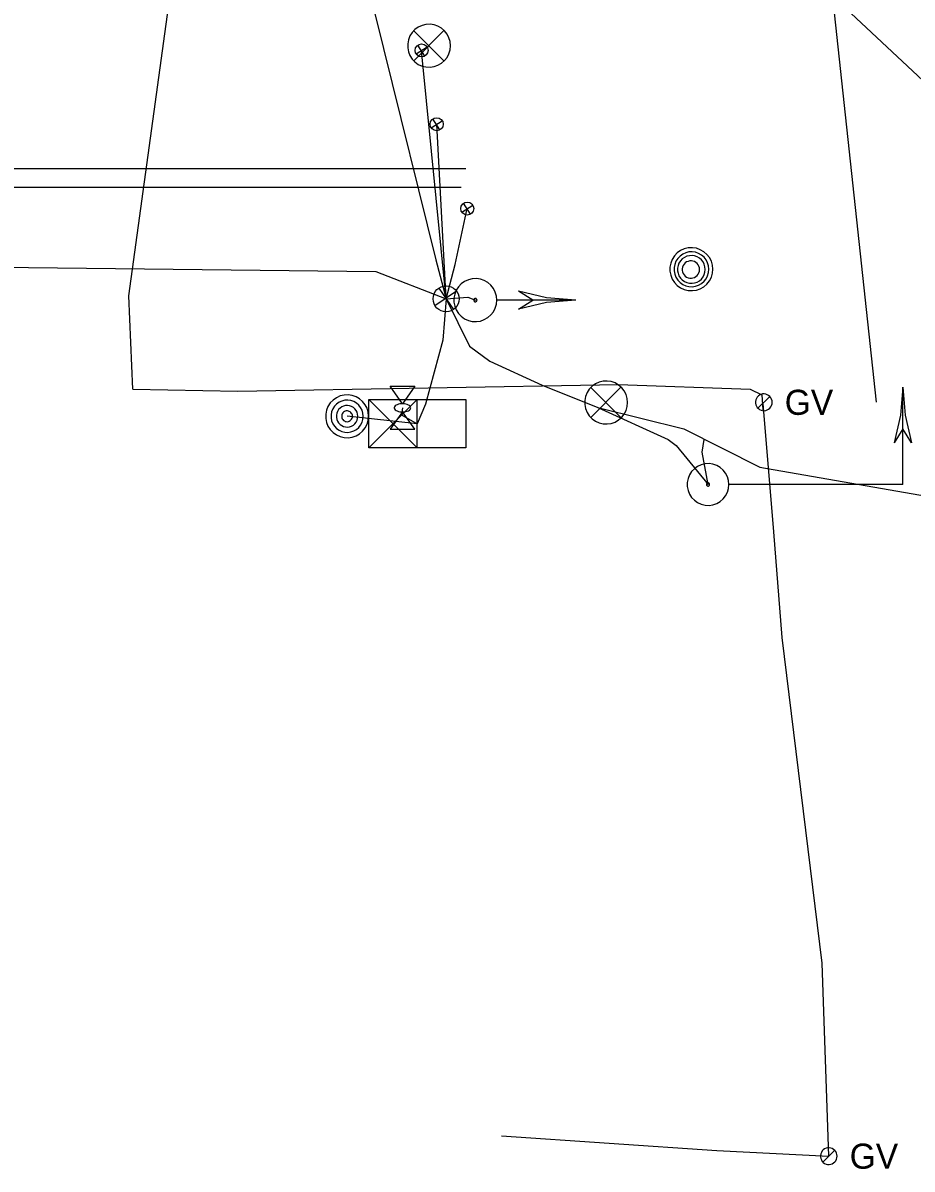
# Model space of a CAD drawing. Extents: x 600849 to 606371, y 330010 to 403088.
# Drawn here: x 604922.6 to 605059.1, y 349725.2 to 349901.2 of the extents above; entities that cross this region are included whole.
import ezdxf

# ---------------------------------------------------------------- set-up
doc = ezdxf.new("R2010")
doc.units = 0
for name, color, linetype in [('E_MISCPROP', 7, 'Continuous'), ('E_SIG', 7, 'Continuous'), ('E_SIG_Conduit', 7, 'Continuous'), ('E_UTL_AG', 7, 'Continuous'), ('E_UTL_E_UG', 7, 'Continuous'), ('E_UTL_G', 7, 'Continuous'), ('E_UTL_G_UG', 7, 'Continuous'), ('E_UTL_Loop_UG', 7, 'Continuous'), ('E_UTL_MH', 7, 'Continuous'), ('E_UTL_Overhead', 7, 'Continuous'), ('E_UTL_T_UG', 7, 'Continuous')]:
    doc.layers.add(name, color=color, linetype=linetype)

# ---------------------------------------------------------------- blocks, each defined once
blk = doc.blocks.new('_U336')
at = {"layer": 'E_SIG'}
for p, q in [((-6.1, 0.4), (6.1, 0.4)), ((0, 6.1), (0, -6.1))]:
    blk.add_line(p, q, dxfattribs=at)
blk.add_circle((0, 0), 6.1, dxfattribs=at)
blk = doc.blocks.new('_U337')
at = {"layer": 'E_SIG'}
for p, q in [((-6.1, 0.4), (6.1, 0.4)), ((0, 6.1), (0, -6.1))]:
    blk.add_line(p, q, dxfattribs=at)
blk.add_circle((0, 0), 6.1, dxfattribs=at)
blk = doc.blocks.new('_U338')
at = {"layer": 'E_SIG'}
for p, q in [((-6.1, 0.4), (6.1, 0.4)), ((0, 6.1), (0, -6.1))]:
    blk.add_line(p, q, dxfattribs=at)
blk.add_circle((0, 0), 6.1, dxfattribs=at)
blk = doc.blocks.new('_U347')
at = {"layer": 'E_SIG'}
for p, q in [((0, 6.1), (0, -6.1)), ((-6.09, 0.4), (6.1, 0.4))]:
    blk.add_line(p, q, dxfattribs=at)
blk.add_circle((0, 0.01), 6.1, dxfattribs=at)

msp = doc.modelspace()

# ---------------------------------------------------------------- linework, layer by layer
at = {"layer": 'E_MISCPROP'}
for points in [[(604975.67, 349840.79), (604975.61, 349841.41), (604975.44, 349842.01), (604975.15, 349842.57), (604974.76, 349843.06), (604974.29, 349843.48), (604973.74, 349843.79), (604973.15, 349843.99), (604972.53, 349844.08), (604971.9, 349844.05), (604971.29, 349843.91), (604970.72, 349843.64), (604970.21, 349843.28), (604969.78, 349842.83), (604969.44, 349842.3), (604969.21, 349841.72), (604969.09, 349841.1), (604969.09, 349840.47), (604969.21, 349839.86), (604969.44, 349839.27), (604969.78, 349838.75), (604970.21, 349838.29), (604970.72, 349837.93), (604971.29, 349837.67), (604971.9, 349837.52), (604972.53, 349837.49), (604973.15, 349837.58), (604973.74, 349837.79), (604974.29, 349838.1), (604974.76, 349838.51), (604975.15, 349839), (604975.44, 349839.56), (604975.61, 349840.16), (604975.67, 349840.79)], [(604974.85, 349840.79), (604974.8, 349841.26), (604974.67, 349841.71), (604974.45, 349842.13), (604974.16, 349842.5), (604973.81, 349842.8), (604973.4, 349843.04), (604972.95, 349843.19), (604972.49, 349843.26), (604972.02, 349843.24), (604971.56, 349843.13), (604971.13, 349842.93), (604970.75, 349842.66), (604970.43, 349842.32), (604970.17, 349841.92), (604970, 349841.48), (604969.91, 349841.02), (604969.91, 349840.55), (604970, 349840.09), (604970.17, 349839.65), (604970.43, 349839.26), (604970.75, 349838.92), (604971.13, 349838.64), (604971.56, 349838.45), (604972.02, 349838.34), (604972.49, 349838.31), (604972.95, 349838.38), (604973.4, 349838.54), (604973.81, 349838.77), (604974.16, 349839.08), (604974.45, 349839.45), (604974.67, 349839.87), (604974.8, 349840.32), (604974.85, 349840.79)], [(604974.02, 349840.79), (604973.99, 349841.1), (604973.9, 349841.4), (604973.76, 349841.68), (604973.57, 349841.93), (604973.33, 349842.13), (604973.06, 349842.29), (604972.76, 349842.39), (604972.45, 349842.44), (604972.14, 349842.42), (604971.83, 349842.35), (604971.55, 349842.22), (604971.29, 349842.03), (604971.07, 349841.81), (604970.9, 349841.54), (604970.79, 349841.25), (604970.73, 349840.94), (604970.73, 349840.63), (604970.79, 349840.32), (604970.9, 349840.03), (604971.07, 349839.77), (604971.29, 349839.54), (604971.55, 349839.36), (604971.83, 349839.23), (604972.14, 349839.15), (604972.45, 349839.14), (604972.76, 349839.18), (604973.06, 349839.29), (604973.33, 349839.44), (604973.57, 349839.65), (604973.76, 349839.9), (604973.9, 349840.17), (604973.99, 349840.47), (604974.02, 349840.79)], [(604973.2, 349840.79), (604973.18, 349840.94), (604973.14, 349841.09), (604973.07, 349841.23), (604972.97, 349841.36), (604972.85, 349841.46), (604972.71, 349841.54), (604972.57, 349841.59), (604972.41, 349841.61), (604972.25, 349841.6), (604972.1, 349841.57), (604971.96, 349841.5), (604971.83, 349841.41), (604971.72, 349841.3), (604971.64, 349841.17), (604971.58, 349841.02), (604971.55, 349840.87), (604971.55, 349840.71), (604971.58, 349840.55), (604971.64, 349840.41), (604971.72, 349840.28), (604971.83, 349840.16), (604971.96, 349840.07), (604972.1, 349840.01), (604972.25, 349839.97), (604972.41, 349839.96), (604972.57, 349839.99), (604972.71, 349840.04), (604972.85, 349840.12), (604972.97, 349840.22), (604973.07, 349840.34), (604973.14, 349840.48), (604973.18, 349840.63), (604973.2, 349840.79)]]:
    msp.add_lwpolyline(points, dxfattribs=at)
at = {"layer": 'E_SIG'}
for points in [[(604988.25, 349897.66), (604988.19, 349898.29), (604988.01, 349898.89), (604987.73, 349899.45), (604987.34, 349899.94), (604986.87, 349900.35), (604986.32, 349900.66), (604985.73, 349900.87), (604985.11, 349900.96), (604984.48, 349900.93), (604983.87, 349900.78), (604983.3, 349900.52), (604982.79, 349900.16), (604982.36, 349899.7), (604982.02, 349899.17), (604981.78, 349898.59), (604981.67, 349897.98), (604981.67, 349897.35), (604981.78, 349896.73), (604982.02, 349896.15), (604982.36, 349895.62), (604982.79, 349895.17), (604983.3, 349894.8), (604983.87, 349894.54), (604984.48, 349894.4), (604985.11, 349894.37), (604985.73, 349894.46), (604986.32, 349894.66), (604986.87, 349894.97), (604987.34, 349895.38), (604987.73, 349895.88), (604988.01, 349896.44), (604988.19, 349897.04), (604988.25, 349897.66)], [(604987.21, 349900), (604982.6, 349895.34)], [(604982.6, 349899.95), (604987.26, 349895.3)], [(604995.36, 349858.62), (604995.3, 349859.24), (604995.12, 349859.85), (604994.83, 349860.4), (604994.44, 349860.9), (604993.97, 349861.31), (604993.43, 349861.62), (604992.83, 349861.83), (604992.21, 349861.92), (604991.59, 349861.89), (604990.98, 349861.74), (604990.41, 349861.48), (604989.89, 349861.11), (604989.46, 349860.66), (604989.12, 349860.13), (604988.89, 349859.55), (604988.77, 349858.93), (604988.77, 349858.31), (604988.89, 349857.69), (604989.12, 349857.11), (604989.46, 349856.58), (604989.89, 349856.13), (604990.41, 349855.76), (604990.98, 349855.5), (604991.59, 349855.35), (604992.21, 349855.32), (604992.83, 349855.41), (604993.43, 349855.62), (604993.97, 349855.93), (604994.44, 349856.34), (604994.83, 349856.84), (604995.12, 349857.39), (604995.3, 349858), (604995.36, 349858.62)], [(605000.86, 349858.62), (604998.66, 349860)], [(605007.46, 349858.62), (605003, 349858.97), (604998.66, 349859.99)], [(604992.31, 349858.62), (604992.3, 349858.67), (604992.29, 349858.71), (604992.27, 349858.76), (604992.24, 349858.79), (604992.2, 349858.83), (604992.16, 349858.85), (604992.12, 349858.87), (604992.07, 349858.87), (604992.02, 349858.87), (604991.97, 349858.86), (604991.93, 349858.84), (604991.89, 349858.81), (604991.86, 349858.78), (604991.83, 349858.74), (604991.81, 349858.69), (604991.8, 349858.64), (604991.8, 349858.6), (604991.81, 349858.55), (604991.83, 349858.5), (604991.86, 349858.46), (604991.89, 349858.43), (604991.93, 349858.4), (604991.97, 349858.38), (604992.02, 349858.37), (604992.07, 349858.37), (604992.12, 349858.37), (604992.16, 349858.39), (604992.2, 349858.41), (604992.24, 349858.45), (604992.27, 349858.48), (604992.29, 349858.53), (604992.3, 349858.57), (604992.31, 349858.62)], [(605007.46, 349858.62), (604995.41, 349858.62)], [(605007.46, 349858.62), (605003, 349858.27), (604998.66, 349857.24)], [(604998.66, 349857.25), (605000.86, 349858.62)], [(605015.43, 349842.9), (605015.37, 349843.53), (605015.19, 349844.13), (605014.91, 349844.69), (605014.52, 349845.18), (605014.04, 349845.59), (605013.5, 349845.91), (605012.91, 349846.11), (605012.29, 349846.2), (605011.66, 349846.17), (605011.05, 349846.02), (605010.48, 349845.76), (605009.97, 349845.4), (605009.53, 349844.94), (605009.2, 349844.42), (605008.96, 349843.83), (605008.84, 349843.22), (605008.84, 349842.59), (605008.96, 349841.97), (605009.2, 349841.39), (605009.53, 349840.86), (605009.97, 349840.41), (605010.48, 349840.05), (605011.05, 349839.79), (605011.66, 349839.64), (605012.29, 349839.61), (605012.91, 349839.7), (605013.5, 349839.9), (605014.04, 349840.22), (605014.52, 349840.63), (605014.91, 349841.12), (605015.19, 349841.68), (605015.37, 349842.28), (605015.43, 349842.9)], [(605014.39, 349845.24), (605009.78, 349840.58)], [(605009.78, 349845.19), (605014.43, 349840.54)], [(605057.66, 349845.27), (605057.33, 349840.95), (605056.33, 349836.73)], [(605057.66, 349830.32), (605057.66, 349845.27)], [(605057.66, 349845.27), (605058, 349840.95), (605059, 349836.73)], [(604975.72, 349835.94), (604975.72, 349843.37)], [(604975.72, 349843.37), (604990.57, 349843.37)], [(604983.14, 349843.37), (604975.72, 349835.94)], [(604975.72, 349843.37), (604983.14, 349835.94)], [(604983.14, 349835.94), (604983.14, 349843.37)], [(604990.57, 349843.37), (604990.57, 349835.94)], [(604983.14, 349839.65), (604983.14, 349839.65)], [(605057.66, 349838.86), (605056.33, 349836.73)], [(605059, 349836.73), (605057.66, 349838.86)], [(604990.57, 349835.94), (604975.72, 349835.94)], [(605030.97, 349830.32), (605030.91, 349830.93), (605030.74, 349831.51), (605030.46, 349832.05), (605030.09, 349832.53), (605029.63, 349832.93), (605029.1, 349833.24), (605028.52, 349833.43), (605027.92, 349833.52), (605027.31, 349833.49), (605026.72, 349833.35), (605026.17, 349833.1), (605025.67, 349832.74), (605025.25, 349832.3), (605024.92, 349831.79), (605024.7, 349831.22), (605024.58, 349830.63), (605024.58, 349830.02), (605024.7, 349829.42), (605024.92, 349828.85), (605025.25, 349828.34), (605025.67, 349827.9), (605026.17, 349827.55), (605026.72, 349827.3), (605027.31, 349827.15), (605027.92, 349827.12), (605028.52, 349827.21), (605029.1, 349827.41), (605029.63, 349827.71), (605030.09, 349828.11), (605030.46, 349828.59), (605030.74, 349829.13), (605030.91, 349829.72), (605030.97, 349830.32)], [(605028.01, 349830.32), (605028.01, 349830.37), (605028, 349830.41), (605027.98, 349830.45), (605027.95, 349830.49), (605027.91, 349830.52), (605027.87, 349830.54), (605027.83, 349830.56), (605027.78, 349830.57), (605027.73, 349830.56), (605027.69, 349830.55), (605027.65, 349830.53), (605027.61, 349830.51), (605027.58, 349830.47), (605027.55, 349830.43), (605027.53, 349830.39), (605027.53, 349830.35), (605027.53, 349830.3), (605027.53, 349830.25), (605027.55, 349830.21), (605027.58, 349830.17), (605027.61, 349830.14), (605027.65, 349830.11), (605027.69, 349830.09), (605027.73, 349830.08), (605027.78, 349830.08), (605027.83, 349830.08), (605027.87, 349830.1), (605027.91, 349830.12), (605027.95, 349830.15), (605027.98, 349830.19), (605028, 349830.23), (605028.01, 349830.28), (605028.01, 349830.32)], [(605057.66, 349830.32), (605031.03, 349830.32)], [(605050.19, 349830.32), (605050.19, 349830.32)]]:
    msp.add_lwpolyline(points, dxfattribs=at)
at = {"layer": 'E_SIG_Conduit'}
for points in [[(604969.92, 349929.73), (604985.98, 349864.78), (604987.57, 349858.81)], [(604741.42, 349865.71), (604976.78, 349863.03)], [(604976.78, 349863.03), (604987.57, 349858.81), (604990.92, 349859.08), (604992.06, 349858.62)], [(604987.57, 349858.81), (604991.15, 349851.56), (604994.26, 349849.24), (605002.31, 349845.56), (605010.87, 349842.14), (605024.06, 349838.86), (605035.73, 349832.96), (605069.52, 349827.11), (605072.1, 349826.97), (605134.18, 349822.56), (605136.25, 349822.64)], [(605010.87, 349842.14), (605021.65, 349837.24), (605022.86, 349836.32), (605027.77, 349830.32)], [(605027.77, 349830.32), (605026.86, 349835.29), (605027.19, 349837.2)]]:
    msp.add_lwpolyline(points, dxfattribs=at)
at = {"layer": 'E_UTL_AG'}
for points in [[(604978.97, 349845.39), (604982.78, 349845.39)], [(604980.88, 349842.72), (604978.97, 349845.39)], [(604982.78, 349845.39), (604980.88, 349842.72)], [(604982.15, 349842.09), (604982.12, 349842.21), (604982.05, 349842.32), (604981.94, 349842.43), (604981.79, 349842.52), (604981.61, 349842.6), (604981.4, 349842.66), (604981.17, 349842.7), (604980.94, 349842.72), (604980.69, 349842.71), (604980.46, 349842.69), (604980.24, 349842.64), (604980.04, 349842.57), (604979.88, 349842.48), (604979.75, 349842.38), (604979.66, 349842.26), (604979.61, 349842.15), (604979.61, 349842.02), (604979.66, 349841.91), (604979.75, 349841.79), (604979.88, 349841.69), (604980.04, 349841.61), (604980.24, 349841.54), (604980.46, 349841.49), (604980.69, 349841.46), (604980.94, 349841.45), (604981.17, 349841.47), (604981.4, 349841.51), (604981.61, 349841.57), (604981.79, 349841.65), (604981.94, 349841.74), (604982.05, 349841.85), (604982.12, 349841.97), (604982.15, 349842.09)], [(604980.88, 349841.45), (604978.97, 349838.79)], [(604982.78, 349838.79), (604980.88, 349841.45)], [(604978.97, 349838.79), (604982.78, 349838.79)]]:
    msp.add_lwpolyline(points, dxfattribs=at)
at = {"layer": 'E_UTL_E_UG'}
for points in [[(604987.57, 349858.81), (604987.07, 349852.47), (604984.41, 349842.64), (604983.14, 349839.65)], [(604980.88, 349842.09), (604980.73, 349840.99), (604983.14, 349839.65), (604972.37, 349840.79)]]:
    msp.add_lwpolyline(points, dxfattribs=at)
at = {"layer": 'E_UTL_G'}
for points in [[(605037.61, 349842.94), (605037.59, 349843.18), (605037.52, 349843.41), (605037.41, 349843.63), (605037.26, 349843.82), (605037.07, 349843.98), (605036.86, 349844.1), (605036.63, 349844.18), (605036.39, 349844.22), (605036.15, 349844.21), (605035.91, 349844.15), (605035.69, 349844.05), (605035.49, 349843.91), (605035.32, 349843.73), (605035.19, 349843.52), (605035.1, 349843.3), (605035.05, 349843.06), (605035.05, 349842.81), (605035.1, 349842.57), (605035.19, 349842.35), (605035.32, 349842.14), (605035.49, 349841.97), (605035.69, 349841.82), (605035.91, 349841.72), (605036.15, 349841.67), (605036.39, 349841.65), (605036.63, 349841.69), (605036.86, 349841.77), (605037.07, 349841.89), (605037.26, 349842.05), (605037.41, 349842.24), (605037.52, 349842.46), (605037.59, 349842.69), (605037.61, 349842.94)], [(605035.42, 349842.03), (605037.24, 349843.84)], [(605047.59, 349727.22), (605047.56, 349727.47), (605047.5, 349727.7), (605047.38, 349727.92), (605047.23, 349728.11), (605047.05, 349728.27), (605046.84, 349728.39), (605046.61, 349728.47), (605046.36, 349728.51), (605046.12, 349728.49), (605045.88, 349728.44), (605045.66, 349728.33), (605045.46, 349728.19), (605045.3, 349728.02), (605045.16, 349727.81), (605045.07, 349727.59), (605045.03, 349727.35), (605045.03, 349727.1), (605045.07, 349726.86), (605045.16, 349726.64), (605045.3, 349726.43), (605045.46, 349726.25), (605045.66, 349726.11), (605045.88, 349726.01), (605046.12, 349725.95), (605046.36, 349725.94), (605046.61, 349725.98), (605046.84, 349726.06), (605047.05, 349726.18), (605047.23, 349726.34), (605047.38, 349726.53), (605047.5, 349726.75), (605047.56, 349726.98), (605047.59, 349727.22)], [(605045.4, 349726.32), (605047.21, 349728.13)]]:
    msp.add_lwpolyline(points, dxfattribs=at)
at = {"layer": 'E_UTL_G_UG'}
for points in [[(605053.61, 349842.94), (605039.42, 349974.87)], [(604939.48, 349844.93), (604938.89, 349859.3), (604948.31, 349927.83), (604948.15, 349952.82)], [(604939.48, 349844.93), (604955.62, 349844.62), (605014.04, 349845.69), (605034.23, 349844.97), (605036.01, 349844.09), (605036.2, 349841.8)], [(604996.09, 349730.36), (605029.14, 349728.11), (605046.3, 349727.22), (605045.31, 349756.83), (605039.16, 349806.86), (605037.85, 349823.07), (605036.21, 349842.73)]]:
    msp.add_lwpolyline(points, dxfattribs=at)
at = {"layer": 'E_UTL_Loop_UG'}
for points in [[(604987.57, 349858.81), (604983.81, 349896.95)], [(604987.57, 349858.81), (604986.12, 349885.62)], [(604987.57, 349858.81), (604988.97, 349864.07), (604990.82, 349872.67)]]:
    msp.add_lwpolyline(points, dxfattribs=at)
at = {"layer": 'E_UTL_MH'}
for points in [[(605028.51, 349863.36), (605028.45, 349863.99), (605028.28, 349864.59), (605027.99, 349865.15), (605027.6, 349865.64), (605027.13, 349866.05), (605026.58, 349866.36), (605025.99, 349866.57), (605025.37, 349866.66), (605024.74, 349866.63), (605024.13, 349866.48), (605023.56, 349866.22), (605023.05, 349865.86), (605022.62, 349865.4), (605022.28, 349864.87), (605022.05, 349864.29), (605021.93, 349863.68), (605021.93, 349863.05), (605022.05, 349862.43), (605022.28, 349861.85), (605022.62, 349861.32), (605023.05, 349860.87), (605023.56, 349860.5), (605024.13, 349860.24), (605024.74, 349860.1), (605025.37, 349860.07), (605025.99, 349860.16), (605026.58, 349860.36), (605027.13, 349860.67), (605027.6, 349861.09), (605027.99, 349861.58), (605028.28, 349862.14), (605028.45, 349862.74), (605028.51, 349863.36)], [(605027.9, 349863.36), (605027.85, 349863.86), (605027.71, 349864.35), (605027.47, 349864.81), (605027.16, 349865.21), (605026.77, 349865.54), (605026.33, 349865.79), (605025.85, 349865.96), (605025.35, 349866.03), (605024.84, 349866.01), (605024.35, 349865.89), (605023.88, 349865.68), (605023.47, 349865.38), (605023.12, 349865.01), (605022.84, 349864.58), (605022.65, 349864.11), (605022.56, 349863.61), (605022.56, 349863.1), (605022.65, 349862.6), (605022.84, 349862.13), (605023.12, 349861.7), (605023.47, 349861.34), (605023.88, 349861.04), (605024.35, 349860.83), (605024.84, 349860.71), (605025.35, 349860.68), (605025.85, 349860.76), (605026.33, 349860.92), (605026.77, 349861.18), (605027.16, 349861.51), (605027.47, 349861.91), (605027.71, 349862.36), (605027.85, 349862.85), (605027.9, 349863.36)], [(605027.34, 349863.33), (605027.3, 349863.73), (605027.18, 349864.12), (605027, 349864.48), (605026.75, 349864.8), (605026.44, 349865.06), (605026.09, 349865.27), (605025.71, 349865.4), (605025.31, 349865.46), (605024.9, 349865.44), (605024.51, 349865.34), (605024.14, 349865.17), (605023.81, 349864.94), (605023.53, 349864.65), (605023.31, 349864.31), (605023.16, 349863.93), (605023.09, 349863.53), (605023.09, 349863.13), (605023.16, 349862.73), (605023.31, 349862.35), (605023.53, 349862.01), (605023.81, 349861.72), (605024.14, 349861.49), (605024.51, 349861.32), (605024.9, 349861.22), (605025.31, 349861.2), (605025.71, 349861.26), (605026.09, 349861.39), (605026.44, 349861.6), (605026.75, 349861.86), (605027, 349862.18), (605027.18, 349862.54), (605027.3, 349862.93), (605027.34, 349863.33)], [(605026.48, 349863.31), (605026.46, 349863.57), (605026.38, 349863.81), (605026.27, 349864.03), (605026.11, 349864.23), (605025.92, 349864.4), (605025.7, 349864.53), (605025.46, 349864.61), (605025.21, 349864.64), (605024.96, 349864.63), (605024.71, 349864.57), (605024.48, 349864.47), (605024.28, 349864.32), (605024.1, 349864.14), (605023.96, 349863.92), (605023.87, 349863.69), (605023.82, 349863.44), (605023.82, 349863.19), (605023.87, 349862.94), (605023.96, 349862.7), (605024.1, 349862.49), (605024.28, 349862.31), (605024.48, 349862.16), (605024.71, 349862.06), (605024.96, 349862), (605025.21, 349861.98), (605025.46, 349862.02), (605025.7, 349862.1), (605025.92, 349862.23), (605026.11, 349862.39), (605026.27, 349862.59), (605026.38, 349862.82), (605026.46, 349863.06), (605026.48, 349863.31)]]:
    msp.add_lwpolyline(points, dxfattribs=at)
at = {"layer": 'E_UTL_Overhead'}
msp.add_lwpolyline([(604968.56, 349978.6), (605140.32, 349817.89)], dxfattribs=at)
at = {"layer": 'E_UTL_T_UG'}
for points in [[(604648.72, 349878.82), (604990.59, 349878.82)], [(604651.26, 349875.93), (604989.88, 349875.93)]]:
    msp.add_lwpolyline(points, dxfattribs=at)

# ---------------------------------------------------------------- block references
at = {"layer": 'E_SIG_Conduit'}
for name, p, xscale, yscale, rotation in [('_U337', (604986.12, 349885.62), 0.16404166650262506, 0.16404166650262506, 122.69997330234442), ('_U338', (604990.82, 349872.67), 0.16404166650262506, 0.16404166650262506, 122.69997330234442), ('_U347', (604987.57, 349858.81), 0.32808333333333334, 0.3280833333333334, 34.193210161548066)]:
    msp.add_blockref(name, p, dxfattribs=dict(at, xscale=xscale, yscale=yscale, rotation=rotation))
at = {"layer": 'E_UTL_Loop_UG', "xscale": 0.16404166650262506, "yscale": 0.16404166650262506, "rotation": 122.69997330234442}
msp.add_blockref('_U336', (604983.81, 349896.95), dxfattribs=at)

# ---------------------------------------------------------------- texts
at = {"layer": 'E_UTL_G'}
for p in [(605039.54, 349841.01), (605049.51, 349725.3)]:
    msp.add_text('GV', height=3.85, dxfattribs=at).set_placement(p)

doc.saveas('drawing.dxf')
